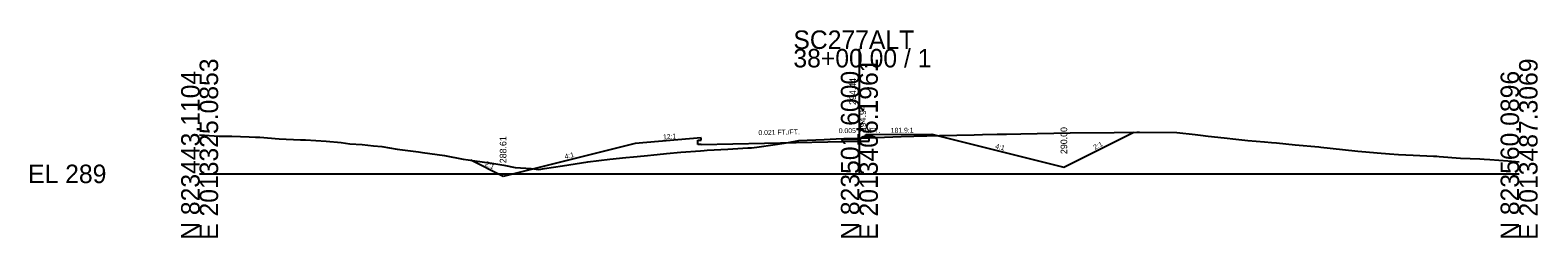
# Model space of a CAD drawing. Extents: x 205929 to 2357175, y -1785700 to 827636.
# Drawn here: x 2018394.5 to 2018623, y 826034.6 to 826066 of the extents above; entities that cross this region are included whole.
import ezdxf

# ---------------------------------------------------------------- set-up
doc = ezdxf.new("R2010")
doc.units = 0
for name, color, linetype in [('RD_GPK_XS_Cell', 7, 'Continuous'), ('RD_XS_Base', 7, 'Continuous'), ('RD_XS_EarthShd', 7, 'Continuous'), ('RD_XS_ExGround', 7, 'Continuous'), ('RD_XS_Pave', 7, 'Continuous'), ('RD_XS_TieSlope', 7, 'Continuous'), ('RD_XS_TX_Elev_EX', 7, 'Continuous'), ('RD_XS_TX_Elev_PR', 7, 'Continuous'), ('RD_XS_TX_ShdSlope', 7, 'Continuous'), ('RD_XS_TX_Slope', 7, 'Continuous')]:
    doc.layers.add(name, color=color, linetype=linetype)

msp = doc.modelspace()

# ---------------------------------------------------------------- linework, layer by layer
at = {"layer": 'RD_GPK_XS_Cell'}
for p, q in [((2018520.17, 826044.26), (2018520.17, 826063.19)), ((2018420.17, 826044.26), (2018520.17, 826044.26)), ((2018520.17, 826044.26), (2018620.17, 826044.26))]:
    msp.add_line(p, q, dxfattribs=at)
at = {"layer": 'RD_XS_Base'}
for p, q in [((2018496.17, 826048.7), (2018520.17, 826049.2)), ((2018520.17, 826049.2), (2018521.17, 826049.2))]:
    msp.add_line(p, q, dxfattribs=at)
at = {"layer": 'RD_XS_EarthShd'}
for p, q in [((2018496.17, 826049.7), (2018486.17, 826048.87)), ((2018521.17, 826050.2), (2018531.17, 826050.26))]:
    msp.add_line(p, q, dxfattribs=at)
at = {"layer": 'RD_XS_ExGround'}
msp.add_lwpolyline([(2018420.17, 826050.15), (2018423.13, 826049.99), (2018425.04, 826049.96), (2018427.69, 826049.87), (2018428.62, 826049.84), (2018429.29, 826049.8), (2018432.2, 826049.58), (2018435.45, 826049.43), (2018435.78, 826049.42), (2018436.24, 826049.4), (2018439.37, 826049.22), (2018441.62, 826049), (2018442.95, 826048.82), (2018444.79, 826048.69), (2018446.53, 826048.52), (2018447.78, 826048.42), (2018450.11, 826047.99), (2018453.34, 826047.61), (2018453.95, 826047.52), (2018457.27, 826047.06), (2018460.11, 826046.48), (2018460.86, 826046.37), (2018461.89, 826046.22), (2018464.44, 826045.89), (2018466.28, 826045.58), (2018468.02, 826045.22), (2018470.44, 826045.07), (2018471.6, 826044.94), (2018472.44, 826045.07), (2018475.18, 826045.5), (2018478.99, 826046.1), (2018482.35, 826046.47), (2018484.77, 826046.72), (2018485.93, 826046.83), (2018487.53, 826046.99), (2018489.51, 826047.2), (2018490.93, 826047.34), (2018493.09, 826047.54), (2018496.08, 826047.77), (2018496.67, 826047.81), (2018497.1, 826047.84), (2018500.25, 826048.02), (2018503.26, 826048.18), (2018503.84, 826048.22), (2018504.63, 826048.32), (2018507.42, 826048.7), (2018509.43, 826049.03), (2018511, 826049.3), (2018514.85, 826049.47), (2018516.67, 826049.56), (2018517.83, 826049.61), (2018520.17, 826049.69), (2018526.52, 826049.92), (2018532.31, 826050.05), (2018537.57, 826050.17), (2018538.81, 826050.2), (2018541.06, 826050.25), (2018541.95, 826050.27), (2018542.45, 826050.28), (2018544.64, 826050.33), (2018552.1, 826050.49), (2018558.77, 826050.54), (2018562.24, 826050.57), (2018562.64, 826050.56), (2018568.31, 826050.52), (2018571.07, 826050.22), (2018571.89, 826050.12), (2018573.02, 826049.99), (2018575.47, 826049.71), (2018577.24, 826049.52), (2018579.05, 826049.32), (2018581.57, 826049.11), (2018582.63, 826049.03), (2018583.4, 826048.95), (2018586.21, 826048.67), (2018589.8, 826048.33), (2018590.12, 826048.3), (2018593.38, 826047.94), (2018595.73, 826047.72), (2018596.96, 826047.58), (2018598.67, 826047.45), (2018600.54, 826047.31), (2018601.89, 826047.21), (2018604.12, 826047.08), (2018607.21, 826046.95), (2018607.7, 826046.93), (2018608.06, 826046.9), (2018611.29, 826046.66), (2018614.22, 826046.52), (2018614.87, 826046.5), (2018615.76, 826046.43), (2018618.45, 826046.23), (2018620.17, 826046.09)], dxfattribs=at)
at = {"layer": 'RD_XS_Pave'}
for p, q in [((2018495.67, 826049.36), (2018496.17, 826049.37)), ((2018496.17, 826049.37), (2018496.17, 826049.7)), ((2018521.17, 826049.87), (2018521.17, 826050.2)), ((2018521.67, 826049.88), (2018521.17, 826049.87)), ((2018521.67, 826049.21), (2018521.67, 826049.88)), ((2018495.67, 826048.69), (2018495.67, 826049.36)), ((2018496.17, 826048.7), (2018495.67, 826048.69)), ((2018521.17, 826049.2), (2018521.67, 826049.21))]:
    msp.add_line(p, q, dxfattribs=at)
at = {"layer": 'RD_XS_TieSlope'}
for p, q in [((2018531.17, 826050.26), (2018551.17, 826045.26)), ((2018551.17, 826045.26), (2018561.78, 826050.56)), ((2018486.17, 826048.87), (2018466.17, 826043.87)), ((2018466.17, 826043.87), (2018461.29, 826046.31))]:
    msp.add_line(p, q, dxfattribs=at)

# ---------------------------------------------------------------- texts
at = {"layer": 'RD_GPK_XS_Cell'}
for s, p in [('SC277ALT', (2018510.17, 826063.19)), ('38+00.00 / 1', (2018510.17, 826060.39)), ('EL 289', (2018394.17, 826042.86))]:
    msp.add_text(s, height=2.8, dxfattribs=at).set_placement(p)
for s, p in [('E 2013325.0853', (2018422.97, 826034.26)), ('E 2013406.1961', (2018522.97, 826034.26)), ('E 2013487.3069', (2018622.97, 826034.26)), ('N 823443.1104', (2018420.17, 826034.26)), ('N 823501.6000', (2018520.17, 826034.26)), ('N 823560.0896', (2018620.17, 826034.26))]:
    msp.add_text(s, height=2.8, rotation=90, dxfattribs=at).set_placement(p)
at = {"layer": 'RD_XS_TX_Elev_EX'}
msp.add_text('294.44', height=1, rotation=90, dxfattribs=at).set_placement((2018519.67, 826054.69))
at = {"layer": 'RD_XS_TX_Elev_PR'}
for s, p in [(' 294.94', (2018521.17, 826050.2)), ('288.61', (2018466.67, 826045.87)), ('290.00', (2018551.67, 826047.26))]:
    msp.add_text(s, height=1, rotation=90, dxfattribs=at).set_placement(p)
at = {"layer": 'RD_XS_TX_ShdSlope'}
for s, rotation, p in [('12:1', 4.7636, (2018490.44, 826049.47)), ('181.9:1', 0.315, (2018524.93, 826050.48))]:
    msp.add_text(s, height=0.75, rotation=rotation, dxfattribs=at).set_placement(p)
at = {"layer": 'RD_XS_TX_Slope'}
for s, rotation, p in [('0.021 FT./FT.', 1.1916, (2018504.88, 826050.13)), ('0.005 FT./FT.', 0.315, (2018517.05, 826050.43)), ('4:1', 14.0362, (2018475.6, 826046.48)), ('4:1', 345.9638, (2018540.72, 826048.13)), ('2:1', 26.5651, (2018555.86, 826047.88)), ('2:1', 333.4349, (2018463.34, 826045.56))]:
    msp.add_text(s, height=0.75, rotation=rotation, dxfattribs=at).set_placement(p)

doc.saveas('drawing.dxf')
